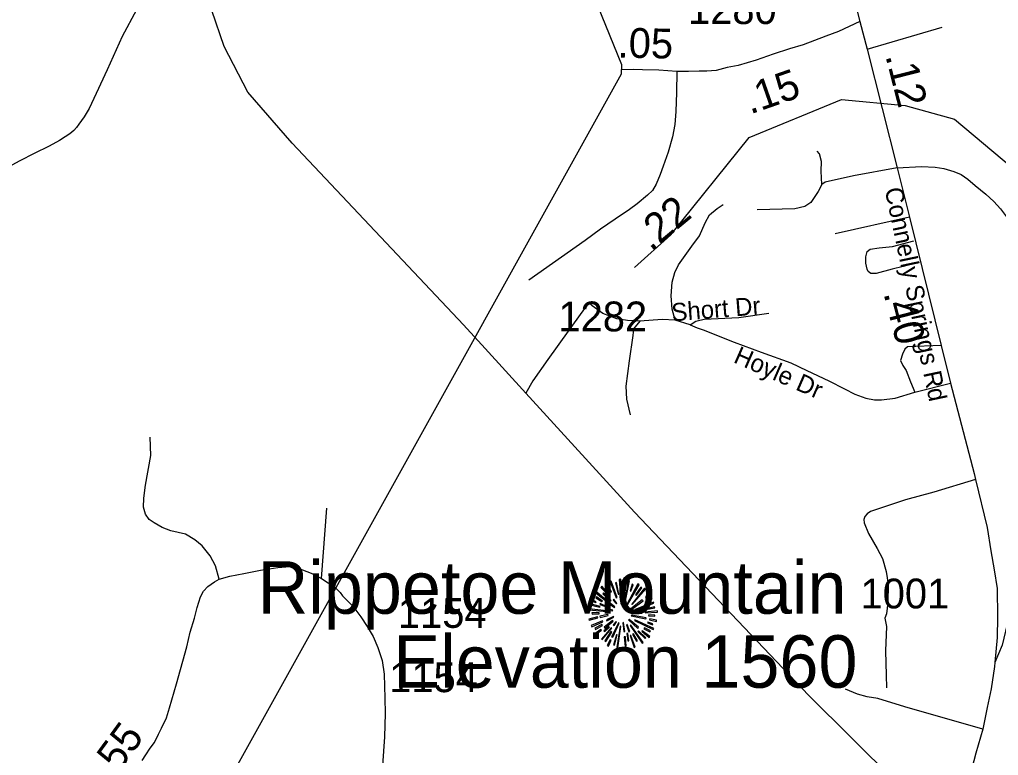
# Model space of a CAD drawing. Extents: x 1159738 to 1321356, y 736314 to 882035.
# Drawn here: x 1244144 to 1248250, y 775673 to 778758 of the extents above; entities that cross this region are included whole.
import ezdxf

# ---------------------------------------------------------------- set-up
doc = ezdxf.new("R2010")
doc.units = 0
for name, color, linetype in [('Exist Boundary Political City Limit New', 7, 'Continuous'), ('Exist Geographical Mountain Summit CELL', 7, 'Continuous'), ('Exist Geographical Mountain Summit Elevation Number Label', 7, 'Continuous'), ('Exist Geographical Mountain Summit Label', 7, 'Continuous'), ('Exist Hydrographic Misc Water Feature', 7, 'Continuous'), ('Exist Road Non-System Type 51', 7, 'Continuous'), ('Exist Road Non-System Type 51 Label', 7, 'Continuous'), ('Exist Road Secondary Mileage Hundredths English Label', 7, 'Continuous'), ('Exist Road Secondary Type 51 Attributed', 7, 'Continuous'), ('Exist Road Secondary Type 51 Label', 7, 'Continuous'), ('Exist Road Secondary Type 51 Number Label', 7, 'Continuous'), ('Exist Utilities Electrical Transmission Line', 7, 'Continuous'), ('Map Preparation Boundary City Limit Buffer Line', 7, 'Continuous')]:
    doc.layers.add(name, color=color, linetype=linetype)

msp = doc.modelspace()

# ---------------------------------------------------------------- linework, layer by layer
at = {"layer": 'Exist Boundary Political City Limit New'}
for points in [[(1246668.5, 778530.8), (1246670.7, 778568.5), (1246268.1, 779559.4)], [(1248892.1, 764635.7), (1246253, 767750.5), (1245595.8, 767446.1), (1245679.1, 768440.4), (1245290.2, 770016.4), (1245100.6, 770927.8), (1244344.9, 774320.4), (1244352.7, 774361.5), (1246668.5, 778530.8)]]:
    msp.add_lwpolyline(points, dxfattribs=at)
at = {"layer": 'Exist Geographical Mountain Summit CELL'}
for points in [[(1246659.5, 776410.5), (1246663.5, 776358.6), (1246666.7, 776359), (1246665.3, 776411.6)], [(1246582.4, 776377.9), (1246618.4, 776340.4), (1246621.7, 776342.9), (1246586.5, 776382.6)], [(1246610, 776379.3), (1246625.6, 776357.5), (1246627.5, 776359), (1246614, 776383.3)], [(1246620.9, 776401.1), (1246647.1, 776334.2), (1246650, 776335.3), (1246626, 776403.6)], [(1246654.7, 776349.1), (1246657.3, 776349.9), (1246648.2, 776397.8), (1246643.8, 776396.7)], [(1246675.5, 776356.4), (1246679.4, 776356.4), (1246683.1, 776403.6), (1246677.6, 776403.6)], [(1246687.5, 776328), (1246702.4, 776405.1), (1246696.9, 776406.9), (1246684.2, 776328.8)], [(1246690.7, 776306.2), (1246693.6, 776304.4), (1246742.3, 776389.1), (1246736.8, 776392.8)], [(1246705.2, 776363.3), (1246708.5, 776362.2), (1246718, 776389.1), (1246713.2, 776390.9)], [(1246711.8, 776307.7), (1246714, 776305.5), (1246769.6, 776369.8), (1246765.6, 776374.6)], [(1246749.2, 776379.3), (1246728.1, 776345.9), (1246731.1, 776344.7), (1246753.5, 776376.1)], [(1246539.2, 776323.3), (1246561.7, 776314.6), (1246562.8, 776317.5), (1246540.6, 776328.4)], [(1246561, 776334.2), (1246586.8, 776317.9), (1246589, 776320.5), (1246563.9, 776338.2)], [(1246562.1, 776353.1), (1246601.7, 776322.6), (1246603.9, 776324.8), (1246565.7, 776357.5)], [(1246590.4, 776350.2), (1246623.1, 776321.1), (1246625.3, 776323.3), (1246593.3, 776355.3)], [(1246633.7, 776324.8), (1246647.5, 776308.4), (1246649.6, 776310.6), (1246636.9, 776327.7)], [(1246664.9, 776337.2), (1246666.3, 776308.1), (1246668.9, 776308.4), (1246668.9, 776337.5)], [(1246769.6, 776312.8), (1246797.2, 776327.7), (1246794.3, 776332.8), (1246768.2, 776315.3)], [(1246769.6, 776335.7), (1246771.4, 776333.2), (1246794.3, 776349.5), (1246790.6, 776353.1)], [(1246533.7, 776283), (1246605.7, 776276.1), (1246606, 776279), (1246533.7, 776288)], [(1246536.3, 776304), (1246577.7, 776294.6), (1246578.8, 776297.9), (1246537.4, 776308.8)], [(1246577.7, 776306.2), (1246608.2, 776294.3), (1246609.3, 776296.4), (1246579.9, 776310.3)], [(1246614, 776311.7), (1246639.1, 776292.8), (1246641.2, 776295.7), (1246616.6, 776314.9)], [(1246614.4, 776281.9), (1246631.5, 776279.7), (1246631.9, 776281.9), (1246615.1, 776286.2)], [(1246708.5, 776287.7), (1246710.3, 776285.2), (1246759, 776321.1), (1246755.8, 776325.5)], [(1246725.5, 776284.8), (1246726.7, 776282.6), (1246804.8, 776311.3), (1246803, 776316)], [(1246771.4, 776284.8), (1246808.1, 776291.4), (1246806.6, 776296.8), (1246770, 776287)], [(1246532.3, 776245.2), (1246533.7, 776240.1), (1246569.7, 776250.7), (1246567.5, 776253.9)], [(1246545.8, 776265.6), (1246575.5, 776267), (1246575.5, 776270.6), (1246544.6, 776270.6)], [(1246578.1, 776256.5), (1246579.1, 776251.7), (1246612.2, 776260.1), (1246611.5, 776263.8)], [(1246605.7, 776242.3), (1246607.9, 776237.6), (1246636.6, 776252.8), (1246635.5, 776256.1)], [(1246709.9, 776258.3), (1246770.7, 776246.3), (1246771.8, 776250.7), (1246711, 776261.9)], [(1246724.5, 776272.1), (1246724.5, 776269.2), (1246754.7, 776269.2), (1246755.4, 776274.2)], [(1246767.8, 776271), (1246820.1, 776274.2), (1246820.4, 776279), (1246768.2, 776274.2)], [(1246782.7, 776259), (1246809.2, 776256.8), (1246809.2, 776261.2), (1246783.1, 776262.2)], [(1246786.7, 776241.9), (1246815, 776234.6), (1246815.7, 776240.1), (1246787.7, 776246.3)], [(1246542, 776217.5), (1246544.6, 776212.9), (1246590.1, 776232.8), (1246588.6, 776237.6)], [(1246559.5, 776201.6), (1246588.6, 776218.3), (1246586.5, 776221.9), (1246557.3, 776206.6)], [(1246584.2, 776161.2), (1246587.1, 776158.7), (1246627.9, 776206.3), (1246624.9, 776208.4)], [(1246599.5, 776192.5), (1246618.8, 776210.7), (1246615.4, 776212.9), (1246595.1, 776195.8)], [(1246595.8, 776211.1), (1246598.7, 776207.4), (1246633.3, 776235.8), (1246631.5, 776238.3)], [(1246627.5, 776171.1), (1246631.9, 776169.3), (1246658.4, 776227.7), (1246655.9, 776228.5)], [(1246634.4, 776220.5), (1246637.6, 776217.5), (1246647.8, 776233.9), (1246646, 776235.4)], [(1246648.9, 776125.7), (1246653.6, 776124.5), (1246666.3, 776213.9), (1246663.1, 776214.7)], [(1246674.4, 776229.6), (1246678.3, 776192.5), (1246682.7, 776192.8), (1246677.6, 776230.3)], [(1246690.4, 776220.9), (1246699.1, 776191), (1246703.1, 776192.8), (1246692.5, 776221.9)], [(1246698.8, 776241.2), (1246737.2, 776205.9), (1246739.8, 776210.3), (1246700.6, 776243.4)], [(1246704.9, 776218.6), (1246755.4, 776143.8), (1246759, 776146.7), (1246707.4, 776219.7)], [(1246723.7, 776238.7), (1246801.9, 776200.5), (1246803.7, 776205.9), (1246725.3, 776241.6)], [(1246763, 776204.5), (1246788.1, 776191.4), (1246790.6, 776195.1), (1246765.2, 776208.4)], [(1246777.2, 776228.5), (1246798.3, 776220.5), (1246800.1, 776224.9), (1246778.6, 776231.7)], [(1246553.3, 776180.9), (1246556.2, 776176.8), (1246584.6, 776198), (1246582, 776201.2)], [(1246624.2, 776192.5), (1246599.1, 776153.3), (1246602.4, 776150.7), (1246628.2, 776190.3)], [(1246639.1, 776135.8), (1246651.1, 776178.7), (1246647.5, 776179.1), (1246634.7, 776136.8)], [(1246680.5, 776171.1), (1246684.2, 776128.6), (1246688.2, 776129.6), (1246684.9, 776171.1)], [(1246700.2, 776154.3), (1246694.7, 776184.2), (1246691.4, 776184.2), (1246695.8, 776153.3)], [(1246704.9, 776175.8), (1246722.3, 776126), (1246726.7, 776127.8), (1246707.8, 776176.5)], [(1246715.4, 776181.6), (1246731.4, 776152.1), (1246735.4, 776154.3), (1246719.1, 776183.1)], [(1246737.2, 776192.8), (1246767.4, 776163.8), (1246770.7, 776166.4), (1246739.4, 776195.4)], [(1246753.9, 776193.6), (1246784.5, 776167.8), (1246787.7, 776171.4), (1246755.8, 776196.2)], [(1246609.3, 776134), (1246614, 776131.1), (1246624.9, 776155.8), (1246621.7, 776158)]]:
    msp.add_lwpolyline(points, close=True, dxfattribs=at)
at = {"layer": 'Exist Hydrographic Misc Water Feature'}
msp.add_lwpolyline([(1246723.1, 777718.2), (1246876.2, 777856.3), (1247204.2, 778263.3), (1247591.1, 778422.9), (1247858.2, 778397.9), (1248065.2, 778341.2), (1248309.2, 778136.1), (1248624.2, 778028), (1248899.1, 778045.5), (1249583.2, 778363.3), (1249776.1, 778408.7), (1250367.2, 778367.3), (1250677.1, 778443.1), (1251025.2, 778659.3), (1251261.1, 778759.6), (1251389.2, 778881.8), (1251778.2, 779415.6)], dxfattribs=at)
at = {"layer": 'Exist Road Non-System Type 51'}
for p, q in [((1247698.5, 778634.2), (1248014.2, 778725.8)), ((1247876.8, 777929.5), (1247564.3, 777859.6)), ((1247898.9, 777196), (1248049, 777234.1)), ((1245411, 776414.5), (1245432.8, 776710.5))]:
    msp.add_line(p, q, dxfattribs=at)
for points in [[(1247508.8, 778067.4), (1247505.7, 778122.4), (1247507.2, 778162.6), (1247499.5, 778195.3), (1247488.8, 778207.2)], [(1247825.5, 778136.6), (1247642.2, 778103.1), (1247522.6, 778076.3), (1247508.8, 778067.4)], [(1247508.8, 778067.4), (1247493.4, 778037.6), (1247462.7, 777991.5), (1247438.2, 777975.1), (1247395.2, 777964.7), (1247237.3, 777960.2)], [(1246894.1, 777497.5), (1246881.2, 777544.1), (1246877, 777600.6), (1246881.2, 777657.1), (1246892.2, 777698.4), (1246907.3, 777730.1), (1246963.7, 777808.6), (1246995.4, 777851.3), (1247020.2, 777906.4), (1247038.1, 777939.5), (1247069.7, 777965.7), (1247094.5, 777983.6)], [(1247916.8, 777741.1), (1247850.7, 777723.2), (1247803.9, 777712.2), (1247736.4, 777694.3), (1247714.4, 777694.3), (1247703.4, 777702.6), (1247699.3, 777712.2), (1247693.7, 777737), (1247693.7, 777763.2), (1247699.3, 777786.6), (1247711.6, 777796.2), (1247748.8, 777801.7), (1247805.2, 777807.2), (1247894.7, 777830.7)], [(1246531.3, 777571.9), (1246445.4, 777451.4), (1246359.5, 777333.8), (1246296.6, 777243), (1246267.4, 777192)], [(1246745.3, 777494.5), (1246693.9, 777496), (1246649.4, 777503.4), (1246591.1, 777525.7), (1246545.1, 777558.5), (1246531.3, 777571.9)], [(1246957, 777478.1), (1246980, 777494.5), (1247015.2, 777501.9), (1247161, 777509.4), (1247286.7, 777527.2)], [(1246745.3, 777494.5), (1246719.2, 777461.8), (1246716.1, 777433.5), (1246700.8, 777327.8), (1246687, 777220.7), (1246690.1, 777167.1), (1246705.4, 777101.7)], [(1246957, 777478.1), (1246894.1, 777497.5), (1246838.9, 777500.5), (1246745.3, 777494.5)], [(1246957, 777478.1), (1246986.1, 777466.2), (1247010.6, 777457.3), (1247141, 777405.2), (1247254.5, 777363.6), (1247379.5, 777318.9), (1247445.5, 777287.7), (1247539, 777243), (1247603.5, 777210.3), (1247647.2, 777188), (1247693.2, 777171.6), (1247730, 777164.2), (1247759.1, 777164.2), (1247815.9, 777171.6), (1247898.9, 777196)], [(1248010, 777391.9), (1247868.4, 777385.9), (1247857.7, 777377), (1247847, 777356.1), (1247839.3, 777329.3), (1247848.5, 777308.5), (1247862.3, 777287.7), (1247880.7, 777240.1), (1247898.9, 777196)], [(1244981.8, 776412.8), (1244966.3, 776468.6), (1244943.1, 776509.8), (1244910.2, 776552.4), (1244880, 776577.6), (1244840.3, 776600.2), (1244778.7, 776614.8), (1244743, 776629.5), (1244708.8, 776648.1), (1244688.2, 776662.7), (1244671.8, 776685.3), (1244663.6, 776714.5), (1244664.9, 776751.7), (1244671.8, 776806.2), (1244694.4, 776931.2), (1244691.7, 777006.9)], [(1248153.1, 776830.5), (1247979.3, 776777.3), (1247859.6, 776744.6), (1247712.4, 776695.5), (1247698.6, 776686.5), (1247689.4, 776674.6), (1247684.8, 776662.7), (1247686.3, 776647.9), (1247704.7, 776603.2), (1247741.5, 776540.7), (1247763, 776499.1), (1247778.3, 776444), (1247787.5, 776391.9), (1247786, 776314.6), (1247779.9, 776266.9), (1247773.7, 776249.1), (1247779.9, 776213.4), (1247776, 776112.2), (1247779.1, 776009.5), (1247780.6, 775956)], [(1248183.9, 775782.9), (1247857.3, 775877.1), (1247743.8, 775911.3), (1247699.3, 775918.8), (1247657.9, 775930.7), (1247608.8, 775951.5)]]:
    msp.add_lwpolyline(points, dxfattribs=at)
at = {"layer": 'Exist Road Secondary Type 51 Attributed'}
for points in [[(1247412.1, 779791.9), (1247445.9, 779652), (1247558.6, 779179.6), (1247669, 778749.6)], [(1244634.7, 778799.6), (1244574.8, 778687.3), (1244511.4, 778547.7), (1244466.2, 778448.1), (1244436.1, 778384.9), (1244415.2, 778351), (1244404.2, 778335.1), (1244392.6, 778319.1), (1244383, 778305.8), (1244372, 778293.2), (1244354.9, 778279.3), (1244335.7, 778266), (1244311.7, 778250.7), (1244267.9, 778228.1), (1244204.9, 778196.9), (1244144.9, 778166.3), (1244049, 778114.5)], [(1247669, 778749.6), (1247578.4, 778708.8), (1247525.4, 778688.3), (1247431.2, 778652.7), (1247372.7, 778635.3), (1247305.1, 778612.7), (1247233.1, 778587.5), (1247157.5, 778565.8), (1247111.5, 778556.9), (1247065.5, 778545), (1247027.1, 778542), (1246994.9, 778542), (1246950.4, 778540.5), (1246901.4, 778540.5)], [(1247669, 778749.6), (1247698.5, 778634.2), (1247825.5, 778136.6)], [(1246901.4, 778540.5), (1246824.7, 778546.5), (1246757.2, 778548), (1246717.3, 778549.5), (1246669.7, 778548)], [(1246901.4, 778540.5), (1246899.8, 778452.7), (1246896.8, 778372.4), (1246892.2, 778318.8), (1246882.9, 778266.8), (1246864.5, 778202.8), (1246843.8, 778144), (1246831.6, 778108.3), (1246814.7, 778068.1), (1246799.4, 778041.3), (1246777.9, 778022), (1246734.9, 777986.3), (1246702.7, 777962.5), (1246641.9, 777920.9), (1246581.2, 777879.5), (1246516.2, 777831.4), (1246280.8, 777666.3)], [(1247825.5, 778136.6), (1247926.7, 778142.5), (1247984.6, 778139.5), (1248020.7, 778134.3), (1248062.1, 778121.7), (1248092.8, 778108.3), (1248121.1, 778089.7), (1248152.6, 778062.2), (1248196.3, 778026.5), (1248230.8, 777995.2), (1248258.4, 777965.4), (1248283.7, 777931.2), (1248306.7, 777885.1), (1248314.2, 777852.5), (1248318.6, 777812.9), (1248319, 777790.6), (1248321.7, 777746.7), (1248326.7, 777696.9), (1248331.3, 777649.3), (1248335.9, 777539.1), (1248342.3, 777333.1)], [(1247825.5, 778136.6), (1247876.8, 777929.5), (1248010, 777391.9), (1248049, 777234.1), (1248147.2, 776854.7), (1248153.1, 776830.5), (1248202.4, 776628.5), (1248217.8, 776530.3), (1248231.6, 776451.4), (1248243.8, 776372.6), (1248245.4, 776253.5), (1248243.8, 776167.2), (1248234.4, 776063.5)], [(1248342.3, 777333.1), (1248346.6, 777262.4), (1248352.7, 777113.6), (1248360.4, 776918.7), (1248366.5, 776784.7), (1248369.6, 776710.3), (1248368.1, 776627), (1248369.6, 776601.7), (1248365, 776552.6), (1248349.7, 776497.6), (1248338.9, 776448.5), (1248323.6, 776387.5), (1248306.7, 776311.6), (1248265.3, 776136), (1248234.4, 776063.5)], [(1244658.4, 775651.9), (1244674.2, 775675.9), (1244692, 775703.8), (1244709.8, 775727), (1244727.6, 775762.3), (1244740, 775788.2), (1244759.9, 775830.7), (1244772.7, 775872.5), (1244802.8, 775973.9), (1244846.5, 776128.4), (1244860.2, 776189.5), (1244878, 776249.4), (1244888.9, 776293.2), (1244902.6, 776338.4), (1244916.3, 776362.3), (1244934.2, 776380.9), (1244961.6, 776400.9), (1244981.8, 776412.8), (1245025.9, 776424.8), (1245084.2, 776435.4), (1245155.4, 776450)], [(1245155.4, 776450), (1245228, 776460.7), (1245277.3, 776464.7), (1245313, 776458), (1245367.8, 776436.7), (1245411, 776414.5), (1245466.4, 776378.3), (1245470.5, 776374)], [(1245470.5, 776374), (1245488.3, 776355.7), (1245499.3, 776342.4), (1245541.8, 776298.5), (1245554.3, 776282.5)], [(1245554.3, 776282.5), (1245576, 776254.7), (1245602, 776213.5), (1245626.7, 776172.3), (1245647.2, 776125.8), (1245665.1, 776071.3), (1245674, 776014.1), (1245676, 775913.1), (1245677.4, 775849.3), (1245674.6, 775751), (1245644.5, 775309.7), (1245605.5, 774394)], [(1248234.4, 776063.5), (1248233.1, 776046.7), (1248219.3, 775953), (1248202.4, 775874.1), (1248183.9, 775782.9), (1248154.5, 775682.2), (1248137.6, 775618.2), (1248117.7, 775557.2), (1248100.8, 775514), (1248090.2, 775488.8)]]:
    msp.add_lwpolyline(points, dxfattribs=at)
at = {"layer": 'Exist Utilities Electrical Transmission Line'}
msp.add_line((1246267.4, 777192), (1246096.6, 777379), dxfattribs=at)
for points in [[(1246096.6, 777379), (1246006, 777478.1), (1245288.2, 778240), (1245101, 778454.2), (1245002.9, 778644.7), (1244898.6, 778948.2), (1244859.7, 779042.6)], [(1246267.4, 777192), (1246723.8, 776692.5), (1247453.9, 775924.7), (1247993.8, 775389), (1248006.1, 775360.7)]]:
    msp.add_lwpolyline(points, dxfattribs=at)
at = {"layer": 'Map Preparation Boundary City Limit Buffer Line'}
for points in [[(1246668.5, 778530.8), (1246670.7, 778568.5), (1246268.1, 779559.4)], [(1248892.1, 764635.7), (1246253, 767750.5), (1245595.8, 767446.1), (1245679.1, 768440.4), (1245290.2, 770016.4), (1245100.6, 770927.8), (1244344.9, 774320.4), (1244352.7, 774361.5), (1246668.5, 778530.8)]]:
    msp.add_lwpolyline(points, dxfattribs=at)

# ---------------------------------------------------------------- texts
at = {"layer": 'Exist Geographical Mountain Summit Elevation Number Label'}
msp.add_text('Elevation 1560', height=220, dxfattribs=at).set_placement((1245711.9, 775957.1))
at = {"layer": 'Exist Geographical Mountain Summit Label'}
msp.add_text('Rippetoe Mountain', height=220, dxfattribs=at).set_placement((1245142.6, 776267.3))
at = {"layer": 'Exist Road Non-System Type 51 Label'}
for s, rotation, p in [('Short Dr', 4.5123, (1246881.4, 777493.1)), ('Hoyle Dr', 336.3061, (1247134.4, 777322.5))]:
    msp.add_text(s, height=75, rotation=rotation, dxfattribs=at).set_placement(p)
at = {"layer": 'Exist Road Secondary Mileage Hundredths English Label'}
for s, rotation, p in [('.05', 358.7371, (1246651.5, 778599.5)), ('.12', 284.3162, (1247774.9, 778606.6)), ('.15', 19.2902, (1247208.6, 778360.1)), ('.22', 39.7441, (1246791.7, 777784.5)), ('.40', 284.5054, (1247766.9, 777610.8)), ('.55', 53.9189, (1244533, 775563.4))]:
    msp.add_text(s, height=125, rotation=rotation, dxfattribs=at).set_placement(p)
at = {"layer": 'Exist Road Secondary Type 51 Label'}
msp.add_text('Connelly Springs Rd', height=75, rotation=281.8732, dxfattribs=at).set_placement((1247772.2, 778046.9))
at = {"layer": 'Exist Road Secondary Type 51 Number Label'}
for s, p in [('1280', (1246947.8, 778739.5)), ('1282', (1246404.3, 777451.1)), ('1001', (1247671.3, 776289.6)), ('1154', (1245731, 776208.1)), ('1154', (1245694.5, 775938.5)), ('1154', (1245694.5, 775938.5)), ('1154', (1245694.5, 775938.5)), ('1154', (1245694.5, 775938.5)), ('1154', (1245694.5, 775938.5)), ('1154', (1245694.5, 775938.5)), ('1154', (1245694.5, 775938.5))]:
    msp.add_text(s, height=125, dxfattribs=at).set_placement(p)

doc.saveas('drawing.dxf')
